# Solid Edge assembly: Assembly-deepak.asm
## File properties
Author: MYPC
Template: normal.asm
Last saved by: Cadcim
Revision: 6
Application: Solid Edge
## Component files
Stock_support_base.par
thrust_bearing.par
adjusting_screw_nut.par
support_adjusting_screw.par
support_roller_bracket.par
stock_support_roller.par
adjusting_nut_handle.par
adjusting_screw_guide.par
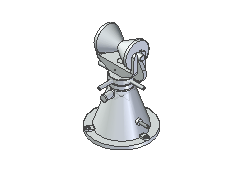
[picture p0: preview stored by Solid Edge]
